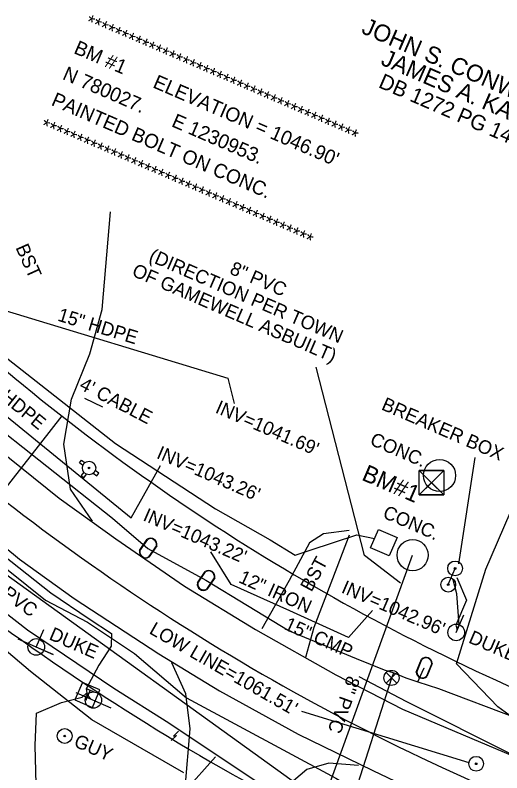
# Model space of a CAD drawing. Extents: x 1230592 to 1231575, y 779497 to 780221.
# Drawn here: x 1230830.6 to 1230974, y 779941.5 to 780164.7 of the extents above; entities that cross this region are included whole.
import ezdxf

# ---------------------------------------------------------------- set-up
doc = ezdxf.new("R2010")
doc.units = 0
for name, color, linetype in [('CTL Bench Mark CELL', 7, 'Continuous'), ('CTL Bench Mark Text', 7, 'Continuous'), ('CTL Sheet Text', 7, 'Continuous'), ('Exist Guardrail', 7, 'Continuous'), ('Exist Horizontal Alignment', 7, 'Continuous'), ('Exist Other Culture Anchor (Guy Wire) CELL', 7, 'Continuous'), ('Exist Other Culture Anchor (Guy Wire) Text', 7, 'Continuous'), ('Exist Other Culture Fence Line', 7, 'Continuous'), ('Exist Other Culture Fence Line Text', 7, 'Continuous'), ('Exist Other Culture Located Object CELL', 7, 'Continuous'), ('Exist Other Culture Located Object Leader', 7, 'Continuous'), ('Exist Other Culture Located Object Text', 7, 'Continuous'), ('Exist Property Deed Book Text', 7, 'Continuous'), ('Exist Property Owner Text', 7, 'Continuous'), ('Exist Right of Way Line', 7, 'Continuous'), ('Exist Right of Way Width CELL', 7, 'Continuous'), ('Exist Roads EOP', 7, 'Continuous'), ('Exist Roads EOP Other', 7, 'Continuous'), ('Exist Roads EOP Other Text', 7, 'Continuous'), ('Exist Roads EOP Text', 7, 'Continuous'), ('Exist Structure Minor Pipes CMP 12 Inch', 7, 'Continuous'), ('Exist Structure Minor Pipes CMP 12 Inch Invert', 7, 'Continuous'), ('Exist Structure Minor Pipes CMP 12 Inch Text', 7, 'Continuous'), ('Exist Structure Minor Pipes CMP 15 Inch', 7, 'Continuous'), ('Exist Structure Minor Pipes CMP 15 Inch Invert', 7, 'Continuous'), ('Exist Structure Minor Pipes CMP 15 Inch Text', 7, 'Continuous'), ('Exist Structure Minor Pipes HDPE 15 Inch', 7, 'Continuous'), ('Exist Structure Minor Pipes HDPE 15 Inch Invert', 7, 'Continuous'), ('Exist Structure Minor Pipes HDPE 15 Inch Leader', 7, 'Continuous'), ('Exist Structure Minor Pipes HDPE 15 Inch Text', 7, 'Continuous'), ('Exist Utilities Other Located Object CELL', 7, 'Continuous'), ('Exist Utilities Other Located Object Leader', 7, 'Continuous'), ('Exist Utilities Other Located Object Text', 7, 'Continuous'), ('Exist Utilities Power Joint Use Telephone CELL', 7, 'Continuous'), ('Exist Utilities Power Pole CELL', 7, 'Continuous'), ('Exist Utilities Power Pole Text', 7, 'Continuous'), ('Exist Utilities Power UG Cable SUE', 7, 'Continuous'), ('Exist Utilities Sanitary Sewer Forced Main SUE', 7, 'Continuous'), ('Exist Utilities Sanitary Sewer UG Line', 7, 'Continuous'), ('Exist Utilities Sanitary Sewer UG Line Leader', 7, 'Continuous'), ('Exist Utilities Sanitary Sewer UG Line Text', 7, 'Continuous'), ('Exist Utilities Telephone Pedestal CELL', 7, 'Continuous'), ('Exist Utilities Telephone Pole CELL', 7, 'Continuous'), ('Exist Utilities Telephone UG Cable SUE', 7, 'Continuous'), ('Exist Utilities Telephone UG FO SUE', 7, 'Continuous'), ('Exist Utilities Water Fire Hydrant CELL', 7, 'Continuous'), ('Exist Utilities Water Meter CELL', 7, 'Continuous'), ('Exist Utilities Water UG Line SUE', 7, 'Continuous'), ('Exist Utilities Water Valve CELL', 7, 'Continuous'), ('Exist Vegetation Woods Line', 7, 'Continuous')]:
    doc.layers.add(name, color=color, linetype=linetype)

msp = doc.modelspace()

# ---------------------------------------------------------------- linework, layer by layer
at = {"layer": 'CTL Bench Mark CELL'}
msp.add_line((1230953.28, 780027.01), (1230953.28, 780027.01), dxfattribs=at)
msp.add_lwpolyline([(1230949.68, 780030.6), (1230956.87, 780030.6), (1230956.87, 780023.41), (1230949.68, 780023.41)], close=True, dxfattribs=at)
for points in [[(1230956.87, 780030.6), (1230949.68, 780023.41), (1230953.27, 780027.01), (1230956.87, 780023.41), (1230949.68, 780030.6)], [(1230953.27, 780027.01), (1230956.87, 780030.6), (1230949.68, 780030.6), (1230953.27, 780027.01)], [(1230953.27, 780027.01), (1230949.68, 780023.41), (1230956.87, 780023.41), (1230953.27, 780027.01)]]:
    msp.add_lwpolyline(points, dxfattribs=at)
at = {"layer": 'Exist Guardrail'}
msp.add_lwpolyline([(1230931.88, 779969.96), (1230945.93, 779962.61), (1230977.49, 779946.73), (1230989.14, 779941.43)], dxfattribs=at)
at = {"layer": 'Exist Horizontal Alignment'}
msp.add_arc((1231236.73, 780547.78), 666.47, 228.49205, 247.86063, dxfattribs=at)
at = {"layer": 'Exist Other Culture Anchor (Guy Wire) CELL'}
for radius in [2.18, 0.24]:
    msp.add_circle((1230845.18, 779952.39), radius, dxfattribs=at)
at = {"layer": 'Exist Other Culture Fence Line'}
msp.add_line((1230856.39, 780049.26), (1230851.17, 780051.77), dxfattribs=at)
msp.add_lwpolyline([(1230880.25, 779941.6), (1230853.18, 779957.14), (1230835.11, 779971.4), (1230810.95, 779991.8), (1230792.98, 780007.87), (1230757.31, 780040.54), (1230719.63, 780075.75), (1230711.33, 780060.3), (1230695.77, 780031.77)], dxfattribs=at)
at = {"layer": 'Exist Other Culture Located Object CELL'}
msp.add_line((1230958.21, 779996.99), (1230960.24, 780001.75), dxfattribs=at)
for centre, radius in [((1230960.24, 780001.75), 2.18), ((1230960.24, 780001.75), 0.24), ((1230958.21, 779996.99), 2.18), ((1230958.21, 779996.99), 0.24)]:
    msp.add_circle(centre, radius, dxfattribs=at)
at = {"layer": 'Exist Other Culture Located Object Leader'}
msp.add_line((1230961.31, 780003.14), (1230966.1, 780034.43), dxfattribs=at)
at = {"layer": 'Exist Right of Way Line'}
for radius, start, end in [(636.47, 228.51644, 247.88383), (696.47, 228.46926, 247.83894)]:
    msp.add_arc((1231236.73, 780547.78), radius, start, end, dxfattribs=at)
at = {"layer": 'Exist Right of Way Width CELL'}
msp.add_line((1230844.35, 780046.65), (1230826.13, 780023.38), dxfattribs=at)
at = {"layer": 'Exist Roads EOP'}
for points in [[(1230745.08, 780109.47), (1230747.52, 780107.09), (1230777.89, 780078.62), (1230784.03, 780072.85), (1230821.26, 780040.32), (1230843.51, 780022.46), (1230853.3, 780015.49), (1230860.24, 780010.5), (1230880.46, 779996.53), (1230901.4, 779983.72), (1230925.05, 779970.38), (1230944.72, 779960.26), (1230989.99, 779941.18)], [(1230853.37, 780015.72), (1230846.94, 780025.11), (1230844.91, 780038.35), (1230847.18, 780051.57), (1230852.58, 780064.99), (1230856.23, 780078.06), (1230858.71, 780106.76)], [(1230728.53, 780092.2), (1230732.49, 780090.47), (1230737.68, 780087.05), (1230769.7, 780057.47), (1230808.1, 780024.07), (1230831.85, 780004.44), (1230847.98, 779992.92), (1230872.92, 779976.6), (1230890.76, 779965.67), (1230913.98, 779952.92), (1230935.97, 779942.19), (1230975.27, 779923.5), (1230980.9, 779919.78)], [(1230929.05, 780012.97), (1230921.5, 780011.98), (1230917.33, 780009.26), (1230911.34, 779998.16), (1230903.29, 779983.98)], [(1230916.22, 779975.61), (1230918.69, 779984.49), (1230924.24, 779998.83), (1230929.12, 780011.61)], [(1230870.11, 779896), (1230876.65, 779917.31), (1230880.73, 779937.02), (1230882.13, 779954.5), (1230880.87, 779964.81), (1230876.78, 779973.99)], [(1230931.76, 779943.75), (1230923.07, 779944.4), (1230916.5, 779942.51), (1230909.37, 779936.41), (1230903.28, 779927.39), (1230895.97, 779906.55), (1230889.52, 779886.21)]]:
    msp.add_lwpolyline(points, dxfattribs=at)
at = {"layer": 'Exist Roads EOP Other'}
msp.add_line((1230937.66, 780013.26), (1230943.21, 780010.88), dxfattribs=at)
msp.add_lwpolyline([(1230943.21, 780010.88), (1230940.79, 780005.43), (1230935.28, 780007.86), (1230937.66, 780013.26)], dxfattribs=at)
for centre, radius in [((1230955.66, 780029.13), 4.73), ((1230947.72, 780005.68), 4.59)]:
    msp.add_circle(centre, radius, dxfattribs=at)
at = {"layer": 'Exist Structure Minor Pipes CMP 12 Inch'}
msp.add_lwpolyline([(1230911.5, 779989.22), (1230894.21, 779997.05)], dxfattribs=at)
at = {"layer": 'Exist Structure Minor Pipes CMP 12 Inch Invert'}
msp.add_lwpolyline([(1230894.21, 779997.05), (1230888.24, 780006.63)], dxfattribs=at)
at = {"layer": 'Exist Structure Minor Pipes CMP 15 Inch'}
msp.add_lwpolyline([(1230928.79, 779981.38), (1230911.5, 779989.22)], dxfattribs=at)
at = {"layer": 'Exist Structure Minor Pipes CMP 15 Inch Invert'}
msp.add_lwpolyline([(1230928.79, 779981.38), (1230935.91, 779989.32)], dxfattribs=at)
at = {"layer": 'Exist Structure Minor Pipes HDPE 15 Inch'}
for p, q in [((1230785.97, 780080.77), (1230864.82, 780016.7)), ((1230816.7, 780081.08), (1230893.31, 780057.75))]:
    msp.add_line(p, q, dxfattribs=at)
at = {"layer": 'Exist Structure Minor Pipes HDPE 15 Inch Leader'}
for points in [[(1230893.31, 780057.75), (1230895.17, 780050.34)], [(1230864.82, 780016.7), (1230873.41, 780032.03)]]:
    msp.add_lwpolyline(points, dxfattribs=at)
at = {"layer": 'Exist Utilities Other Located Object CELL'}
for radius in [2.18, 0.24]:
    msp.add_circle((1230966.44, 779944.22), radius, dxfattribs=at)
at = {"layer": 'Exist Utilities Other Located Object Leader'}
msp.add_line((1230964.36, 779944.5), (1230915.09, 779959.66), dxfattribs=at)
at = {"layer": 'Exist Utilities Power Joint Use Telephone CELL'}
msp.add_line((1230836.81, 779978.62), (1230836.81, 779978.62), dxfattribs=at)
msp.add_lwpolyline([(1230831.36, 779980.98), (1230841.75, 779976.44), (1230836.8, 779978.61), (1230839.04, 779983.79)], dxfattribs=at)
msp.add_circle((1230836.81, 779978.63), 2.45, dxfattribs=at)
at = {"layer": 'Exist Utilities Power Pole CELL'}
for q in [(1230962.83, 779988.06), (1230960.56, 779982.91)]:
    msp.add_line((1230960.56, 779982.91), q, dxfattribs=at)
msp.add_circle((1230960.56, 779982.91), 2.45, dxfattribs=at)
at = {"layer": 'Exist Utilities Power UG Cable SUE'}
msp.add_lwpolyline([(1230960.71, 779999.06), (1230963.6, 779992.39), (1230960.49, 779985.06), (1230960.84, 779983.72)], dxfattribs=at)
at = {"layer": 'Exist Utilities Sanitary Sewer Forced Main SUE'}
msp.add_lwpolyline([(1230757.9, 780125.31), (1230781.72, 780102.58), (1230821.53, 780068.76), (1230860.17, 780038.53), (1230889.66, 780019.35), (1230905.72, 780010.18), (1230913.11, 780005.64), (1230917.57, 780007.15), (1230931.25, 780011.67), (1230936.47, 780010.56)], dxfattribs=at)
at = {"layer": 'Exist Utilities Sanitary Sewer UG Line'}
for p, q in [((1230765.87, 780044.54), (1230919.53, 779934.09)), ((1230922.38, 779935.77), (1230947.72, 780005.68)), ((1230878.76, 779953.81), (1230877.28, 779952.36)), ((1230878.09, 779952.56), (1230876.61, 779951.11)), ((1230877.28, 779952.36), (1230878.09, 779952.56))]:
    msp.add_line(p, q, dxfattribs=at)
at = {"layer": 'Exist Utilities Sanitary Sewer UG Line Leader'}
msp.add_line((1230889.6, 779946.28), (1230840.58, 779891.44), dxfattribs=at)
msp.add_lwpolyline([(1230944.11, 779997.4), (1230933.54, 780005.61), (1230919.26, 780061.06)], dxfattribs=at)
at = {"layer": 'Exist Utilities Telephone Pedestal CELL'}
msp.add_line((1230851.85, 779964.56), (1230851.85, 779964.56), dxfattribs=at)
msp.add_lwpolyline([(1230848.22, 779963.05), (1230853.36, 779960.83), (1230855.58, 779965.96), (1230850.45, 779968.19), (1230848.22, 779963.05)], dxfattribs=at)
at = {"layer": 'Exist Utilities Telephone Pole CELL'}
for p, q in [((1230848.42, 779965.23), (1230858.82, 779960.72)), ((1230853.63, 779962.97), (1230853.63, 779962.97))]:
    msp.add_line(p, q, dxfattribs=at)
msp.add_circle((1230853.63, 779962.97), 2.41, dxfattribs=at)
at = {"layer": 'Exist Utilities Telephone UG Cable SUE'}
for points in [[(1230727.4, 780094.55), (1230764.04, 780059.47), (1230801.45, 780025.84), (1230841.13, 779994.59), (1230852.38, 779986.88), (1230859.01, 779982.58), (1230858.9, 779978.86), (1230855.27, 779973.3), (1230851.52, 779966.28), (1230851.69, 779965.12)], [(1230725.79, 780092.76), (1230762.7, 780057.62), (1230799.95, 780024.08), (1230839.56, 779992.45), (1230851.92, 779985.96), (1230865.71, 779976.72), (1230881.08, 779963.61), (1230925.1, 779940.03), (1230952.92, 779923.05), (1230969.39, 779909.31), (1230971.4, 779908.18)], [(1230960.84, 779983.72), (1230961.47, 779985.11), (1230960.73, 779994.29), (1230959.62, 779998.35)], [(1230835.83, 779896.28), (1230836.44, 779918.41), (1230836.84, 779934.53), (1230836.47, 779949.64), (1230836.9, 779959.16), (1230844.24, 779962.3), (1230850.3, 779963.84), (1230851.69, 779965.12), (1230852.3, 779963.94), (1230852.83, 779963.24)]]:
    msp.add_lwpolyline(points, dxfattribs=at)
at = {"layer": 'Exist Utilities Telephone UG FO SUE'}
msp.add_lwpolyline([(1230717.56, 780084.84), (1230755.17, 780048.89), (1230793.32, 780015.51), (1230834.26, 779983.7), (1230859.68, 779966.46), (1230875.86, 779956.24), (1230911.92, 779932.25), (1230957.32, 779909.15), (1230963.62, 779906.34), (1230967.97, 779905.69), (1230971.46, 779906.77), (1230971.4, 779908.18)], dxfattribs=at)
at = {"layer": 'Exist Utilities Water Fire Hydrant CELL'}
msp.add_line((1230852.37, 780031.34), (1230852.37, 780031.34), dxfattribs=at)
for points in [[(1230850.54, 780032.08), (1230849.51, 780032.86), (1230850.13, 780033.68), (1230851.18, 780032.89)], [(1230850.81, 780030.12), (1230850.04, 780029.1), (1230850.85, 780028.48), (1230851.63, 780029.51)], [(1230853.59, 780029.78), (1230854.62, 780029.01), (1230855.24, 780029.82), (1230854.19, 780030.61)]]:
    msp.add_lwpolyline(points, dxfattribs=at)
for radius in [1.98, 0.243]:
    msp.add_circle((1230852.37, 780031.34), radius, dxfattribs=at)
at = {"layer": 'Exist Utilities Water Meter CELL'}
for p, q in [((1230869.78, 780007.71), (1230869.78, 780007.71)), ((1230886.84, 779998.23), (1230886.84, 779998.23)), ((1230951.15, 779972.48), (1230951.15, 779972.48))]:
    msp.add_line(p, q, dxfattribs=at)
for points in [[(1230867.23, 780006.99), (1230869.53, 780010.35)], [(1230867.34, 780006.91), (1230869.64, 780010.28)], [(1230872.22, 780008.51), (1230869.91, 780005.13)], [(1230872.33, 780008.44), (1230870.02, 780005.05)], [(1230884.29, 779997.5), (1230886.59, 780000.87)], [(1230884.4, 779997.43), (1230886.7, 780000.79)], [(1230889.28, 779999.03), (1230886.97, 779995.64)], [(1230889.39, 779998.95), (1230887.08, 779995.57)], [(1230948.81, 779971.23), (1230950.35, 779975.01)], [(1230948.94, 779971.18), (1230950.48, 779974.95)], [(1230953.37, 779973.77), (1230951.82, 779969.98)], [(1230953.5, 779973.72), (1230951.95, 779969.93)]]:
    msp.add_lwpolyline(points, dxfattribs=at)
for centre, radius, start, end in [((1230870.51, 780008.78), 1.86, 349.3204, 121.9804), ((1230870.52, 780008.79), 1.73, 350.7992, 120.5449), ((1230869.05, 780006.63), 1.86, 168.8501, 301.6515), ((1230869.06, 780006.64), 1.73, 170.973, 299.4544), ((1230887.57, 779999.29), 1.86, 349.3204, 121.9804), ((1230887.58, 779999.3), 1.73, 350.7992, 120.5449), ((1230886.11, 779997.14), 1.86, 168.8501, 301.6515), ((1230886.11, 779997.15), 1.73, 170.973, 299.4544), ((1230951.64, 779973.67), 1.86, 1.4478, 134.1079), ((1230951.65, 779973.68), 1.73, 2.9267, 132.6723), ((1230950.66, 779971.26), 1.86, 180.9775, 313.7789), ((1230950.67, 779971.27), 1.73, 183.1004, 311.5819)]:
    msp.add_arc(centre, radius, start, end, dxfattribs=at)
at = {"layer": 'Exist Utilities Water UG Line SUE'}
for points in [[(1230745.46, 780113.17), (1230770.14, 780090.37), (1230820.51, 780047.2), (1230859.23, 780016.55), (1230869.67, 780007.67), (1230886.8, 779998.27), (1230911.3, 779983.42), (1230931.06, 779975.25), (1230939.35, 779971.91), (1230942.18, 779970.99), (1230945.7, 779969.55), (1230949.24, 779968.31), (1230955.39, 779966.4), (1230978.2, 779957.72), (1230978.2, 779957.72)], [(1230923.13, 779915.15), (1230926.24, 779921.66), (1230941.56, 779969.49), (1230942.18, 779970.99)], [(1230949.24, 779968.31), (1230950.49, 779971.17), (1230951.15, 779972.48)]]:
    msp.add_lwpolyline(points, dxfattribs=at)
at = {"layer": 'Exist Utilities Water Valve CELL'}
msp.add_lwpolyline([(1230943.05, 779971.09), (1230939.9, 779967.94), (1230941.48, 779969.51), (1230943.05, 779967.94), (1230939.9, 779971.09)], dxfattribs=at)
msp.add_circle((1230941.48, 779969.51), 2.23, dxfattribs=at)
at = {"layer": 'Exist Vegetation Woods Line'}
msp.add_lwpolyline([(1230990.12, 779948.41), (1230972.78, 779960.97), (1230960.65, 779973.68), (1230969.25, 780001.55), (1230983.61, 780034.71), (1230987.35, 780047.82)], dxfattribs=at)

# ---------------------------------------------------------------- texts
at = {"layer": 'CTL Bench Mark Text'}
msp.add_text('BM#1', height=5, rotation=336.5812, dxfattribs=at).set_placement((1230932.43, 780027.91))
at = {"layer": 'CTL Sheet Text'}
for s, p in [('****************************************', (1230850.91, 780161.24)), ("BM #1      ELEVATION = 1046.90'", (1230847.59, 780153.59)), ('N 780027.      E 1230953.', (1230844.28, 780145.95)), ('PAINTED BOLT ON CONC.', (1230840.97, 780138.3)), ('****************************************', (1230837.66, 780130.65))]:
    msp.add_text(s, height=4.1667, rotation=336.5812, dxfattribs=at).set_placement(p)
at = {"layer": 'Exist Other Culture Anchor (Guy Wire) Text'}
msp.add_text('GUY', height=4, rotation=336.5812, dxfattribs=at).set_placement((1230847.59, 779949.44))
at = {"layer": 'Exist Other Culture Fence Line Text'}
msp.add_text("4' CABLE", height=4, rotation=332.5897, dxfattribs=at).set_placement((1230849.22, 780054.72))
at = {"layer": 'Exist Other Culture Located Object Text'}
msp.add_text('BREAKER BOX', height=4, rotation=336.5812, dxfattribs=at).set_placement((1230938.25, 780048.65))
at = {"layer": 'Exist Property Deed Book Text'}
msp.add_text('DB 1272 PG 1436', height=4.5, rotation=336.5812, dxfattribs=at).set_placement((1230937.37, 780143.54))
at = {"layer": 'Exist Property Owner Text'}
for s, p in [('JOHN S. CONWAY AND', (1230932.35, 780159.51)), ('JAMES A. KANIPE', (1230938.05, 780150.23))]:
    msp.add_text(s, height=5, rotation=336.5812, dxfattribs=at).set_placement(p)
at = {"layer": 'Exist Roads EOP Other Text'}
for p in [(1230934.85, 780038.31), (1230938.63, 780016.81)]:
    msp.add_text('CONC.', height=4, rotation=336.5812, dxfattribs=at).set_placement(p)
at = {"layer": 'Exist Roads EOP Text'}
for rotation, p in [(294.0555, (1230830.63, 780096.26)), (61.6593, (1230917.91, 779994.61))]:
    msp.add_text('BST', height=4, rotation=rotation, dxfattribs=at).set_placement(p)
at = {"layer": 'Exist Structure Minor Pipes CMP 12 Inch Invert'}
msp.add_text("INV=1043.22'", height=4, rotation=336.5812, dxfattribs=at).set_placement((1230868, 780015.99))
at = {"layer": 'Exist Structure Minor Pipes CMP 12 Inch Text'}
msp.add_text('12" IRON', height=4, rotation=335.635, dxfattribs=at).set_placement((1230896.15, 779997.77))
at = {"layer": 'Exist Structure Minor Pipes CMP 15 Inch Invert'}
msp.add_text("INV=1042.96'", height=4, rotation=336.5812, dxfattribs=at).set_placement((1230926.44, 779994.74))
at = {"layer": 'Exist Structure Minor Pipes CMP 15 Inch Text'}
msp.add_text('15" CMP', height=4, rotation=335.635, dxfattribs=at).set_placement((1230909.61, 779983.96))
at = {"layer": 'Exist Structure Minor Pipes HDPE 15 Inch Invert'}
for s, p in [("INV=1041.69'", (1230889.3, 780047.75)), ("INV=1043.26'", (1230871.99, 780034.34))]:
    msp.add_text(s, height=4, rotation=336.5812, dxfattribs=at).set_placement(p)
at = {"layer": 'Exist Structure Minor Pipes HDPE 15 Inch Text'}
for rotation, p in [(343.0615, (1230842.86, 780074.76)), (320.9034, (1230818.79, 780057.6))]:
    msp.add_text('15" HDPE', height=4, rotation=rotation, dxfattribs=at).set_placement(p)
at = {"layer": 'Exist Utilities Other Located Object Text'}
msp.add_text("LOW LINE=1061.51'", height=4, rotation=330.1648, dxfattribs=at).set_placement((1230869.83, 779982.75))
at = {"layer": 'Exist Utilities Power Pole Text'}
for p in [(1230840.32, 779980.95), (1230963.93, 779980)]:
    msp.add_text('DUKE', height=4, rotation=336.5812, dxfattribs=at).set_placement(p)
at = {"layer": 'Exist Utilities Sanitary Sewer UG Line Text'}
for s, rotation, p in [('(DIRECTION PER TOWN', 336.5812, (1230869.71, 780092.43)), ('OF GAMEWELL ASBUILT)', 336.5812, (1230864.73, 780088.05)), ('8" PVC', 336.5812, (1230893.54, 780088.65)), ('8" PVC', 324.2911, (1230821.22, 779997.36)), ('8" PVC', 250.0702, (1230928.55, 779970.41))]:
    msp.add_text(s, height=4, rotation=rotation, dxfattribs=at).set_placement(p)
at = {"layer": 'Exist Utilities Telephone Pedestal CELL'}
msp.add_text('T', height=3.42, rotation=336.5812, dxfattribs=at).set_placement((1230850.13, 779963.44))

doc.saveas('drawing.dxf')
